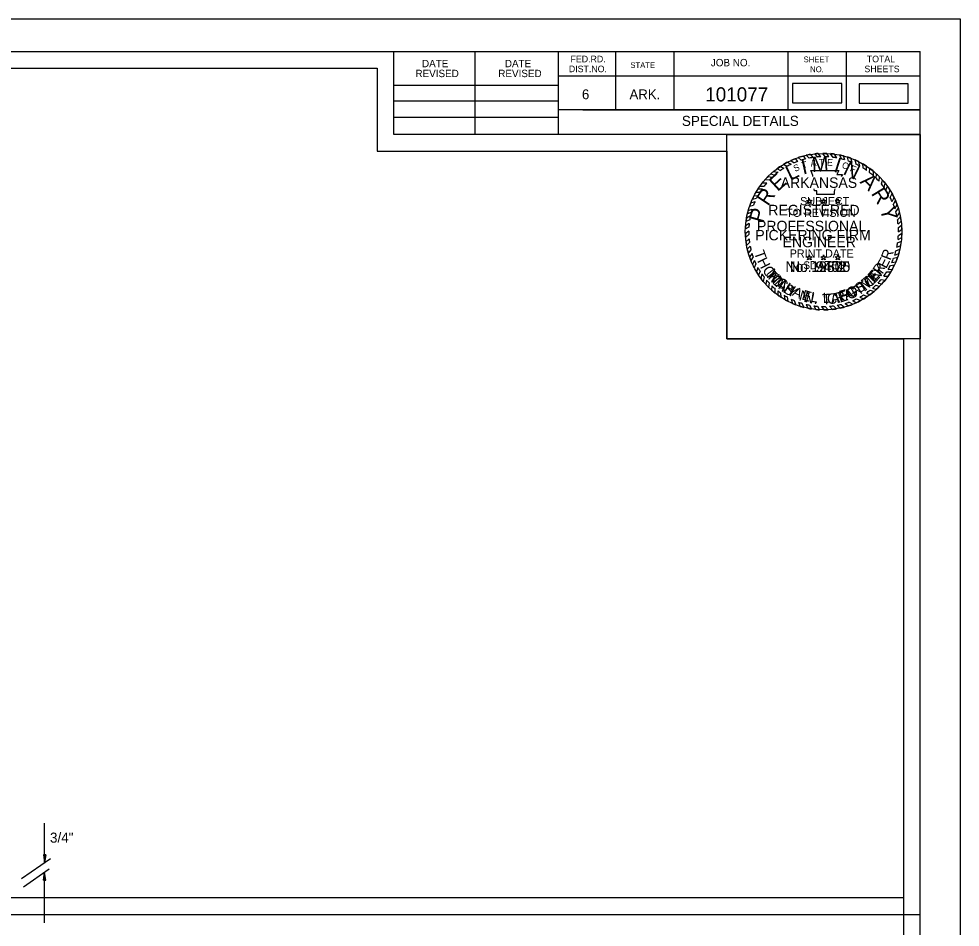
# Model space of a CAD drawing. Extents: x 1372039 to 1372773, y 376713 to 376926.
# Drawn here: x 1372260.6 to 1372372.6, y 376817.9 to 376926 of the extents above; entities that cross this region are included whole.
import ezdxf

# ---------------------------------------------------------------- set-up
doc = ezdxf.new("R2010")
doc.units = 0
for name, color, linetype in [('Default', 7, 'Continuous'), ('R_Border', 7, 'Continuous'), ('R_Border Notes', 7, 'Continuous'), ('R_Border Plan-Plan', 7, 'Continuous'), ('R_No Plot', 7, 'Continuous'), ('STAMP_PE_CRAFTON', 7, 'Continuous'), ('STAMP_PE_FOSTER', 7, 'Continuous'), ('STAMP_PE_SEAL-INFO', 7, 'Continuous'), ('STAMP_PE_TAEGTMEYER', 7, 'Continuous'), ('STAMP_PE_TXT', 7, 'Continuous'), ('STAMP_PRELIMINARY', 7, 'Continuous')]:
    doc.layers.add(name, color=color, linetype=linetype)

msp = doc.modelspace()

# ---------------------------------------------------------------- linework, layer by layer
at = {"layer": 'Default'}
for p, q in [((1372263.67, 376825.56), (1372263.67, 376830.27)), ((1372263.54, 376826.49), (1372263.67, 376825.56)), ((1372263.8, 376826.49), (1372263.54, 376826.49)), ((1372263.58, 376826.49), (1372263.67, 376825.87)), ((1372263.58, 376826.49), (1372263.67, 376825.74)), ((1372263.62, 376826.49), (1372263.67, 376826.19)), ((1372263.62, 376826.49), (1372263.67, 376826.05)), ((1372263.8, 376826.49), (1372263.67, 376825.56)), ((1372263.71, 376826.49), (1372263.67, 376826.19)), ((1372263.76, 376826.49), (1372263.67, 376825.87)), ((1372263.8, 376826.49), (1372263.67, 376825.74)), ((1372263.76, 376826.49), (1372263.67, 376826.05)), ((1372263.67, 376826.49), (1372263.67, 376826.36)), ((1372263.71, 376826.49), (1372263.67, 376826.36)), ((1372260.92, 376823.65), (1372264.38, 376826.05)), ((1372261.18, 376822.68), (1372264.2, 376824.81)), ((1372263.54, 376823.47), (1372263.67, 376824.41)), ((1372263.58, 376823.47), (1372263.67, 376824.28)), ((1372263.67, 376818.37), (1372263.67, 376824.41)), ((1372263.8, 376823.47), (1372263.67, 376824.41)), ((1372263.8, 376823.47), (1372263.67, 376824.28)), ((1372263.54, 376823.47), (1372263.8, 376823.47)), ((1372263.58, 376823.47), (1372263.67, 376824.1)), ((1372263.62, 376823.47), (1372263.67, 376823.96)), ((1372263.62, 376823.47), (1372263.67, 376823.78)), ((1372263.76, 376823.47), (1372263.67, 376824.1)), ((1372263.76, 376823.47), (1372263.67, 376823.96)), ((1372263.71, 376823.47), (1372263.67, 376823.78)), ((1372263.71, 376823.47), (1372263.67, 376823.65)), ((1372263.67, 376823.47), (1372263.67, 376823.65))]:
    msp.add_line(p, q, dxfattribs=at)
for points in [[(1372352.7, 376916.01), (1372358.54, 376916.01), (1372358.54, 376918.32), (1372352.7, 376918.32)], [(1372360.64, 376915.96), (1372366.47, 376915.96), (1372366.47, 376918.27), (1372360.64, 376918.27)]]:
    msp.add_lwpolyline(points, close=True, dxfattribs=at)
at = {"layer": 'R_Border'}
for p, q in [((1372051.71, 376922.11), (1372367.89, 376922.11)), ((1372305.25, 376912.23), (1372305.25, 376922.11)), ((1372314.93, 376912.23), (1372314.93, 376922.11)), ((1372324.79, 376922.11), (1372324.79, 376912.23)), ((1372331.63, 376922.11), (1372331.63, 376915.17)), ((1372338.57, 376922.11), (1372338.57, 376915.17)), ((1372352.15, 376922.11), (1372352.15, 376915.17)), ((1372359.09, 376922.11), (1372359.09, 376915.17)), ((1372367.89, 376716.65), (1372367.89, 376922.11)), ((1372367.89, 376919.17), (1372324.79, 376919.17)), ((1372367.89, 376919.19), (1372367.89, 376919.19)), ((1372305.25, 376918.09), (1372324.79, 376918.09)), ((1372305.25, 376916.23), (1372324.79, 376916.23)), ((1372367.89, 376915.17), (1372324.79, 376915.17)), ((1372327.75, 376915.17), (1372367.89, 376915.17)), ((1372305.25, 376914.29), (1372324.79, 376914.29)), ((1372367.89, 376912.23), (1372305.25, 376912.23))]:
    msp.add_line(p, q, dxfattribs=at)
at = {"layer": 'R_Border Plan-Plan'}
msp.add_line((1372051.71, 376819.38), (1372367.89, 376819.38), dxfattribs=at)
at = {"layer": 'R_No Plot'}
msp.add_line((1372039.31, 376926), (1372372.64, 376926), dxfattribs=at)
for points in [[(1372039.3, 376926), (1372372.64, 376926), (1372372.64, 376712.66), (1372039.3, 376712.66)], [(1372053.71, 376920.11), (1372303.25, 376920.11), (1372303.25, 376910.23), (1372320.79, 376910.23), (1372344.89, 376910.23), (1372344.89, 376887.89), (1372365.89, 376887.89), (1372365.89, 376718.65), (1372053.71, 376718.65)], [(1372365.89, 376821.38), (1372053.71, 376821.38), (1372053.71, 376920.11), (1372303.25, 376920.11), (1372303.25, 376910.23), (1372320.79, 376910.23), (1372344.89, 376910.23), (1372344.89, 376887.89), (1372365.89, 376887.89)], [(1372344.89, 376912.23), (1372367.89, 376912.23), (1372367.89, 376887.89), (1372344.89, 376887.89)]]:
    msp.add_lwpolyline(points, close=True, dxfattribs=at)
at = {"layer": 'STAMP_PE_SEAL-INFO'}
for p, q in [((1372353, 376909.36), (1372353.3, 376909.03)), ((1372353.35, 376909.48), (1372353.73, 376909.18)), ((1372353.94, 376909.67), (1372354.23, 376909.32)), ((1372354.33, 376909.76), (1372354.69, 376909.42)), ((1372354.81, 376909.86), (1372355.11, 376909.49)), ((1372355.33, 376909.93), (1372355.61, 376909.55)), ((1372356.06, 376909.58), (1372355.75, 376909.97)), ((1372356.56, 376909.58), (1372356.28, 376909.99)), ((1372357.02, 376909.56), (1372356.76, 376909.99)), ((1372357.52, 376909.51), (1372357.23, 376909.95)), ((1372357.95, 376909.45), (1372357.69, 376909.9)), ((1372358.51, 376909.33), (1372358.34, 376909.79)), ((1372358.91, 376909.22), (1372358.75, 376909.69)), ((1372359.37, 376909.07), (1372359.22, 376909.55)), ((1372359.78, 376908.91), (1372359.64, 376909.41)), ((1372351.23, 376908.43), (1372351.67, 376908.23)), ((1372351.62, 376908.68), (1372352.05, 376908.45)), ((1372352.06, 376908.93), (1372352.53, 376908.7)), ((1372352.5, 376909.14), (1372352.88, 376908.86)), ((1372360.25, 376908.71), (1372360.14, 376909.2)), ((1372360.69, 376908.48), (1372360.6, 376908.99)), ((1372361.08, 376908.25), (1372361.04, 376908.75)), ((1372361.51, 376907.96), (1372361.48, 376908.48)), ((1372349.75, 376907.22), (1372350.3, 376907.17)), ((1372350.09, 376907.54), (1372350.55, 376907.4)), ((1372350.43, 376907.84), (1372350.96, 376907.74)), ((1372350.81, 376908.17), (1372351.26, 376907.96)), ((1372354.86, 376907.96), (1372358.21, 376907.96)), ((1372354.99, 376907.65), (1372354.86, 376907.96)), ((1372355.09, 376907.36), (1372354.99, 376907.65)), ((1372355.1, 376907.24), (1372355.09, 376907.36)), ((1372358.21, 376907.96), (1372357.98, 376907.47)), ((1372357.98, 376907.47), (1372358.62, 376907.47)), ((1372358.62, 376907.47), (1372358.47, 376907.24)), ((1372361.87, 376907.7), (1372361.91, 376908.18)), ((1372362.32, 376907.33), (1372362.34, 376907.85)), ((1372362.63, 376907.03), (1372362.7, 376907.53)), ((1372362.99, 376906.66), (1372363.06, 376907.19)), ((1372348.81, 376906.09), (1372349.31, 376906.09)), ((1372349.08, 376906.46), (1372349.63, 376906.48)), ((1372349.43, 376906.87), (1372349.95, 376906.83)), ((1372363.27, 376906.34), (1372363.4, 376906.81)), ((1372363.59, 376905.93), (1372363.73, 376906.43)), ((1372363.81, 376905.61), (1372363.99, 376906.07)), ((1372348.09, 376904.92), (1372348.59, 376904.99)), ((1372348.33, 376905.35), (1372348.81, 376905.37)), ((1372348.57, 376905.75), (1372349.09, 376905.78)), ((1372355.29, 376905.53), (1372355.26, 376905.75)), ((1372355.6, 376905.53), (1372355.29, 376905.53)), ((1372355.6, 376905.1), (1372355.6, 376905.53)), ((1372357.63, 376905.1), (1372355.6, 376905.1)), ((1372357.65, 376905.44), (1372357.63, 376905.1)), ((1372357.73, 376905.75), (1372357.65, 376905.44)), ((1372364.12, 376905.11), (1372364.3, 376905.6)), ((1372364.32, 376904.75), (1372364.54, 376905.19)), ((1372347.57, 376903.69), (1372348.06, 376903.83)), ((1372347.72, 376904.1), (1372348.23, 376904.25)), ((1372347.91, 376904.53), (1372348.41, 376904.64)), ((1372364.55, 376904.26), (1372364.77, 376904.75)), ((1372364.69, 376903.93), (1372364.95, 376904.36)), ((1372364.88, 376903.38), (1372365.15, 376903.85)), ((1372347.31, 376902.78), (1372347.78, 376902.98)), ((1372347.42, 376903.19), (1372347.89, 376903.36)), ((1372364.99, 376903.01), (1372365.29, 376903.46)), ((1372365.12, 376902.45), (1372365.44, 376902.9)), ((1372347.53, 376901.64), (1372347.09, 376901.36)), ((1372347.59, 376902.08), (1372347.14, 376901.86)), ((1372347.68, 376902.54), (1372347.21, 376902.29)), ((1372365.19, 376902.07), (1372365.55, 376902.43)), ((1372365.26, 376901.56), (1372365.63, 376901.9)), ((1372347.49, 376901.22), (1372347.07, 376900.96)), ((1372347.48, 376900.73), (1372347.07, 376900.39)), ((1372365.29, 376901.15), (1372365.68, 376901.44)), ((1372365.29, 376900.22), (1372365.71, 376900.5)), ((1372365.3, 376900.63), (1372365.71, 376900.95)), ((1372347.48, 376900.32), (1372347.09, 376899.99)), ((1372347.52, 376899.82), (1372347.15, 376899.47)), ((1372347.57, 376899.39), (1372347.22, 376899.02)), ((1372365.2, 376899.33), (1372365.65, 376899.55)), ((1372365.25, 376899.72), (1372365.69, 376899.97)), ((1372347.65, 376898.93), (1372347.31, 376898.57)), ((1372347.74, 376898.52), (1372347.43, 376898.1)), ((1372365, 376898.38), (1372365.48, 376898.58)), ((1372365.11, 376898.83), (1372365.57, 376899.02)), ((1372347.87, 376898.07), (1372347.57, 376897.65)), ((1372348.01, 376897.65), (1372347.72, 376897.23)), ((1372348.17, 376897.22), (1372347.91, 376896.8)), ((1372364.51, 376896.99), (1372365, 376897.08)), ((1372364.72, 376897.5), (1372365.21, 376897.63)), ((1372364.86, 376897.88), (1372365.35, 376898.08)), ((1372348.34, 376896.84), (1372348.12, 376896.37)), ((1372348.58, 376896.38), (1372348.39, 376895.89)), ((1372348.82, 376895.97), (1372348.63, 376895.5)), ((1372363.9, 376895.87), (1372364.38, 376895.87)), ((1372364.08, 376896.15), (1372364.58, 376896.21)), ((1372364.35, 376896.65), (1372364.84, 376896.72)), ((1372349.02, 376895.66), (1372348.91, 376895.11)), ((1372349.3, 376895.27), (1372349.2, 376894.74)), ((1372349.6, 376894.89), (1372349.52, 376894.37)), ((1372363.26, 376894.98), (1372363.72, 376894.91)), ((1372363.56, 376895.38), (1372364.07, 376895.38)), ((1372349.9, 376894.56), (1372349.84, 376894.03)), ((1372350.23, 376894.23), (1372350.2, 376893.7)), ((1372350.57, 376893.92), (1372350.57, 376893.39)), ((1372361.94, 376893.7), (1372362.41, 376893.55)), ((1372362.21, 376893.92), (1372362.68, 376893.79)), ((1372362.62, 376894.29), (1372363.06, 376894.15)), ((1372362.87, 376894.55), (1372363.35, 376894.47)), ((1372350.93, 376893.62), (1372350.95, 376893.1)), ((1372351.27, 376893.37), (1372351.31, 376892.86)), ((1372351.7, 376893.09), (1372351.76, 376892.58)), ((1372352.05, 376892.89), (1372352.14, 376892.37)), ((1372352.53, 376892.64), (1372352.69, 376892.12)), ((1372360.32, 376892.67), (1372360.8, 376892.46)), ((1372360.72, 376892.88), (1372361.14, 376892.65)), ((1372361.14, 376893.13), (1372361.59, 376892.93)), ((1372361.48, 376893.35), (1372361.92, 376893.16)), ((1372352.9, 376892.47), (1372353.07, 376891.96)), ((1372353.39, 376892.28), (1372353.6, 376891.77)), ((1372353.8, 376892.14), (1372354.03, 376891.65)), ((1372354.31, 376892), (1372354.52, 376891.54)), ((1372354.71, 376891.92), (1372354.96, 376891.46)), ((1372355.21, 376891.84), (1372355.45, 376891.39)), ((1372355.65, 376891.79), (1372355.92, 376891.36)), ((1372356.13, 376891.76), (1372356.43, 376891.35)), ((1372356.59, 376891.76), (1372356.93, 376891.36)), ((1372357.11, 376891.79), (1372357.43, 376891.41)), ((1372357.55, 376891.83), (1372357.92, 376891.47)), ((1372357.99, 376891.9), (1372358.38, 376891.56)), ((1372358.48, 376892.01), (1372358.86, 376891.68)), ((1372358.94, 376892.13), (1372359.36, 376891.83)), ((1372359.44, 376892.29), (1372359.88, 376892.02)), ((1372359.86, 376892.46), (1372360.28, 376892.2))]:
    msp.add_line(p, q, dxfattribs=at)
for radius, start, end in [(9.32, 111.3124, 114.7026), (9.32, 105.2339, 109.0352), (8.91, 104.0352, 107.3615), (9.32, 99.7525, 102.7765), (8.91, 98.258, 101.0329), (9.32, 93.9381, 96.5517), (8.91, 92.1102, 95.0367), (9.32, 87.7298, 90.6707), (8.91, 85.9628, 88.9097), (9.32, 81.9732, 84.8236), (8.91, 79.9264, 82.696), (9.32, 75.3125, 77.9426), (8.91, 73.5575, 76.2314), (9.32, 69.6061, 72.3058), (9.32, 123.6199, 126.5906), (8.91, 121.9746, 125.11), (9.32, 117.6544, 120.8099), (8.91, 115.6869, 119.1583), (8.91, 110.3086, 113.1659), (8.91, 67.6248, 70.504), (9.32, 63.1329, 66.2704), (8.91, 61.1558, 64.3784), (9.32, 56.9003, 60.0942), (8.91, 54.9238, 58.2702), (9.32, 135.4021, 138.3031), (8.91, 133.1331, 136.2562), (9.32, 129.7326, 132.5376), (8.91, 127.5297, 130.9683), (8.91, 48.3016, 52.0395), (9.32, 50.3492, 53.7159), (9.32, 44.3405, 47.3929), (9.32, 141.6056, 144.4486), (8.91, 139.301, 142.5873), (8.91, 42.2212, 45.5512), (8.91, 36.135, 39.5311), (9.32, 38.1247, 41.2316), (9.32, 31.9614, 35.4294), (9.32, 152.864, 155.5189), (9.32, 147.0072, 149.899), (8.91, 151.0315, 153.573), (8.91, 145.0197, 148.2104), (8.91, 29.9032, 33.6645), (9.32, 25.9391, 29.0125), (9.32, 158.4077, 161.0701), (8.91, 156.3402, 159.2319), (8.91, 23.7732, 27.2211), (8.91, 17.6802, 21.4251), (9.32, 19.9538, 23.3141), (9.32, 164.3068, 166.894), (8.91, 162.4331, 165.0013), (8.91, 11.5444, 15.2364), (9.32, 13.8421, 17.4447), (9.32, 170.0003, 172.6878), (8.91, 173.73, 176.4734), (8.91, 167.9048, 170.9039), (8.91, 5.7599, 9.0606), (9.32, 7.5852, 10.8621), (9.32, 175.7409, 178.2066), (9.32, 181.7251, 184.1626), (8.91, 179.6454, 182.2633), (8.91, 359.7329, 3.0639), (9.32, 1.7215, 4.7268), (9.32, 355.7156, 358.9569), (9.32, 187.4204, 190.1927), (8.91, 185.4539, 188.234), (8.91, 348.0778, 351.3435), (8.91, 353.8632, 357.1274), (9.32, 349.8305, 353.0885), (9.32, 193.0369, 195.9973), (8.91, 191.2274, 193.9858), (8.91, 341.777, 345.0925), (9.32, 343.8925, 347.035), (9.32, 198.8967, 201.6281), (8.91, 196.9675, 199.8353), (8.91, 202.7761, 205.4791), (8.91, 335.6038, 339.1858), (9.32, 337.3837, 340.9933), (9.32, 204.5479, 207.4328), (9.32, 210.8636, 213.6571), (8.91, 208.7883, 211.7934), (8.91, 323.5851, 327.4407), (8.91, 329.5549, 333.2076), (9.32, 331.4037, 334.9332), (9.32, 216.6115, 219.491), (8.91, 214.1838, 217.2747), (8.91, 220.3909, 223.3056), (8.91, 316.6531, 320.3711), (9.32, 318.2846, 321.8043), (9.32, 325.4405, 328.9872), (9.32, 222.48, 225.3801), (9.32, 228.3665, 231.348), (8.91, 226.2494, 229.2407), (8.91, 304.823, 308.5143), (8.91, 310.7744, 314.3161), (9.32, 312.4518, 315.6633), (8.91, 232.229, 234.9336), (9.32, 234.295, 236.9452), (8.91, 238.2223, 240.8353), (9.32, 240.1977, 242.8613), (8.91, 244.3204, 246.9486), (8.91, 292.8745, 296.1185), (8.91, 299.0768, 302.1724), (9.32, 300.621, 303.8703), (9.32, 306.3721, 310.208), (9.32, 246.576, 249.1558), (8.91, 250.3491, 253.1216), (9.32, 252.5967, 255.3252), (8.91, 256.505, 259.1192), (9.32, 258.4433, 261.1398), (8.91, 262.3783, 265.2012), (9.32, 264.1978, 267.1009), (8.91, 268.3215, 271.277), (8.91, 274.6157, 277.4486), (9.32, 276.4239, 279.4357), (8.91, 280.3459, 283.5814), (9.32, 282.3199, 285.3702), (8.91, 286.6423, 289.9783), (9.32, 288.5709, 291.9733), (9.32, 294.6481, 298.2166), (9.32, 270.2548, 273.3361)]:
    msp.add_arc((1372356.39, 376900.67), radius, start, end, dxfattribs=at)
at = {"layer": 'STAMP_PE_TXT'}
for p, q in [((1372354.57, 376904.24), (1372354.37, 376904.39)), ((1372354.37, 376904.39), (1372354.62, 376904.39)), ((1372354.49, 376904.01), (1372354.57, 376904.24)), ((1372354.69, 376904.15), (1372354.49, 376904.01)), ((1372354.62, 376904.39), (1372354.69, 376904.62)), ((1372354.69, 376904.62), (1372354.77, 376904.39)), ((1372354.89, 376904.01), (1372354.69, 376904.15)), ((1372354.77, 376904.39), (1372355.01, 376904.39)), ((1372355.01, 376904.39), (1372354.82, 376904.24)), ((1372354.82, 376904.24), (1372354.89, 376904.01)), ((1372356.27, 376904.24), (1372356.07, 376904.39)), ((1372356.07, 376904.39), (1372356.32, 376904.39)), ((1372356.19, 376904.01), (1372356.27, 376904.24)), ((1372356.39, 376904.15), (1372356.19, 376904.01)), ((1372356.32, 376904.39), (1372356.39, 376904.62)), ((1372356.39, 376904.62), (1372356.47, 376904.39)), ((1372356.59, 376904.01), (1372356.39, 376904.15)), ((1372356.47, 376904.39), (1372356.71, 376904.39)), ((1372356.71, 376904.39), (1372356.51, 376904.24)), ((1372356.51, 376904.24), (1372356.59, 376904.01)), ((1372357.97, 376904.24), (1372357.77, 376904.39)), ((1372357.77, 376904.39), (1372358.01, 376904.39)), ((1372357.89, 376904.01), (1372357.97, 376904.24)), ((1372358.09, 376904.15), (1372357.89, 376904.01)), ((1372358.01, 376904.39), (1372358.09, 376904.62)), ((1372358.09, 376904.62), (1372358.16, 376904.39)), ((1372358.29, 376904.01), (1372358.09, 376904.15)), ((1372358.16, 376904.39), (1372358.41, 376904.39)), ((1372358.41, 376904.39), (1372358.21, 376904.24)), ((1372358.21, 376904.24), (1372358.29, 376904.01)), ((1372354.57, 376897.53), (1372354.37, 376897.68)), ((1372354.37, 376897.68), (1372354.62, 376897.68)), ((1372354.49, 376897.3), (1372354.57, 376897.53)), ((1372354.69, 376897.45), (1372354.49, 376897.3)), ((1372354.62, 376897.68), (1372354.69, 376897.91)), ((1372354.69, 376897.91), (1372354.77, 376897.68)), ((1372354.89, 376897.3), (1372354.69, 376897.45)), ((1372354.77, 376897.68), (1372355.01, 376897.68)), ((1372355.01, 376897.68), (1372354.82, 376897.53)), ((1372354.82, 376897.53), (1372354.89, 376897.3)), ((1372356.27, 376897.53), (1372356.07, 376897.68)), ((1372356.07, 376897.68), (1372356.32, 376897.68)), ((1372356.19, 376897.3), (1372356.27, 376897.53)), ((1372356.39, 376897.45), (1372356.19, 376897.3)), ((1372356.32, 376897.68), (1372356.39, 376897.91)), ((1372356.39, 376897.91), (1372356.47, 376897.68)), ((1372356.59, 376897.3), (1372356.39, 376897.45)), ((1372356.47, 376897.68), (1372356.71, 376897.68)), ((1372356.71, 376897.68), (1372356.51, 376897.53)), ((1372356.51, 376897.53), (1372356.59, 376897.3)), ((1372357.97, 376897.53), (1372357.77, 376897.68)), ((1372357.77, 376897.68), (1372358.01, 376897.68)), ((1372357.89, 376897.3), (1372357.97, 376897.53)), ((1372358.09, 376897.45), (1372357.89, 376897.3)), ((1372358.01, 376897.68), (1372358.09, 376897.91)), ((1372358.09, 376897.91), (1372358.16, 376897.68)), ((1372358.29, 376897.3), (1372358.09, 376897.45)), ((1372358.16, 376897.68), (1372358.41, 376897.68)), ((1372358.41, 376897.68), (1372358.21, 376897.53)), ((1372358.21, 376897.53), (1372358.29, 376897.3))]:
    msp.add_line(p, q, dxfattribs=at)
at = {"layer": 'STAMP_PRELIMINARY'}
msp.add_circle((1372356.39, 376900.67), 9.32, dxfattribs=at)

# ---------------------------------------------------------------- texts
at = {"layer": 'Default'}
msp.add_text('3/4"', height=1.2, dxfattribs=at).set_placement((1372264.31, 376827.93))
at = {"layer": 'R_Border'}
for s, height, p in [('DATE', 0.879, (1372308.59, 376920.24)), ('DATE', 0.879, (1372318.45, 376920.24)), ('FED.RD.', 0.782, (1372326.27, 376920.83)), ('STATE', 0.684, (1372333.39, 376920.15)), ('JOB NO.', 0.879, (1372342.97, 376920.35)), ('SHEET', 0.684, (1372354.01, 376920.83)), ('TOTAL', 0.782, (1372361.53, 376920.83)), ('REVISED', 0.879, (1372307.81, 376919.06)), ('REVISED', 0.879, (1372317.67, 376919.06)), ('DIST.NO.', 0.782, (1372326.07, 376919.65)), ('NO.', 0.684, (1372354.79, 376919.65)), ('SHEETS', 0.782, (1372361.25, 376919.65)), ('6', 1.17, (1372327.63, 376916.43)), ('ARK.', 1.172, (1372333.29, 376916.43))]:
    msp.add_text(s, height=height, dxfattribs=at).set_placement(p)
at = {"layer": 'R_Border Notes'}
for s, height, p in [('101077', 1.68, (1372342.3, 376916.17)), ('SPECIAL DETAILS', 1.2, (1372339.52, 376913.25))]:
    msp.add_text(s, height=height, dxfattribs=at).set_placement(p)
at = {"layer": 'STAMP_PE_CRAFTON'}
msp.add_text('No. 12370', height=1.25, dxfattribs=at).set_placement((1372351.85, 376895.87))
for s, rotation, p in [('T', 310.7442, (1372349.36, 376895.57)), ('N', 49.2411, (1372362.67, 376894.69)), ('O', 317.6422, (1372350.02, 376894.76)), ('N', 324.4537, (1372350.87, 376893.97)), ('T', 34.1136, (1372360.97, 376893.31)), ('O', 41.8391, (1372361.83, 376893.91)), ('Y', 331.1686, (1372351.9, 376893.26)), ('A', 20.5125, (1372359.07, 376892.43)), ('F', 28.7821, (1372360.05, 376892.8)), ('N', 347.4752, (1372353.96, 376892.34)), ('C', 6.0117, (1372356.86, 376892.01)), ('R', 14.8189, (1372357.96, 376892.13)), ('.', 356.8926, (1372355.19, 376892.06))]:
    msp.add_text(s, height=1.25, rotation=rotation, dxfattribs=at).set_placement(p)
at = {"layer": 'STAMP_PE_FOSTER'}
msp.add_text('No. 9402', height=1.25, dxfattribs=at).set_placement((1372352.38, 376895.87))
for s, rotation, p in [('M', 308.339, (1372349.51, 376895.69)), ('E', 46.9613, (1372362.39, 376894.66)), ('R', 54.5031, (1372363.12, 376895.48)), ('I', 314.1842, (1372350.3, 376894.75)), ('C', 319.8733, (1372350.66, 376894.4)), ('T', 39.4194, (1372361.53, 376893.91)), ('H', 327.7235, (1372351.59, 376893.66)), ('A', 335.7276, (1372352.57, 376893.08)), ('E', 343.5779, (1372353.71, 376892.61)), ('F', 15.8691, (1372358.43, 376892.42)), ('O', 23.719, (1372359.47, 376892.75)), ('S', 31.7234, (1372360.58, 376893.28)), ('L', 350.8115, (1372354.77, 376892.34)), ('L', 1.2666, (1372356.3, 376892.18)), ('.', 6.8035, (1372357.35, 376892.24))]:
    msp.add_text(s, height=1.2, rotation=rotation, dxfattribs=at).set_placement(p)
at = {"layer": 'STAMP_PE_TAEGTMEYER'}
for s, rotation, p in [('T', 289.646, (1372348.09, 376898.18)), ('R', 69.57, (1372364.34, 376897.18)), ('H', 296.7339, (1372348.45, 376897.2)), ('E', 63.0984, (1372363.84, 376896.2)), ('O', 303.7708, (1372349.04, 376896.09)), ('M', 314.2033, (1372349.69, 376895.14)), ('E', 46.8094, (1372362.43, 376894.45)), ('Y', 53.9986, (1372363.17, 376895.26)), ('A', 321.0594, (1372350.65, 376894.17)), ('M', 39.3, (1372361.39, 376893.57)), ('S', 327.8239, (1372351.48, 376893.53)), ('N', 344.2727, (1372353.38, 376892.52)), ('E', 17.6836, (1372358.34, 376892.2)), ('G', 23.3052, (1372359.39, 376892.53)), ('T', 31.466, (1372360.49, 376893.02)), ('T', 3.0061, (1372356.26, 376891.99)), ('A', 8.9826, (1372357.3, 376892.05)), ('.', 350.6464, (1372354.59, 376892.19))]:
    msp.add_text(s, height=1.25, rotation=rotation, dxfattribs=at).set_placement(p)
msp.add_text('No. 19605', height=1.25, dxfattribs=at).set_placement((1372351.85, 376895.87))
at = {"layer": 'STAMP_PE_TXT'}
for s, rotation, p in [('T', 1.8248, (1372355.86, 376908.53)), ('S', 23.5541, (1372352.99, 376907.77)), ('T', 16.311, (1372353.91, 376908.15)), ('A', 9.0679, (1372354.88, 376908.4)), ('E', 355.2002, (1372356.77, 376908.54)), ('O', 342.2506, (1372358.5, 376908.26)), ('F', 335.0075, (1372359.46, 376907.92))]:
    msp.add_text(s, height=0.781, rotation=rotation, dxfattribs=at).set_placement(p)
for s, p in [('ARKANSAS', (1372351.28, 376905.88)), ('REGISTERED', (1372349.81, 376902.61)), ('PROFESSIONAL', (1372348.46, 376900.71)), ('ENGINEER', (1372351.5, 376898.81))]:
    msp.add_text(s, height=1.25, dxfattribs=at).set_placement(p)
at = {"layer": 'STAMP_PRELIMINARY'}
for s, rotation, p in [('M', 3.1074, (1372355.03, 376907.77)), ('I', 342.3164, (1372357.49, 376907.83)), ('L', 25.513, (1372352.4, 376906.7)), ('I', 12.5248, (1372353.93, 376907.46)), ('N', 333.9382, (1372358.6, 376907.56)), ('E', 42.3578, (1372350.92, 376905.37)), ('A', 315.6579, (1372360.64, 376906.53)), ('R', 301.3831, (1372362, 376905.22)), ('R', 56.2292, (1372349.76, 376903.63)), ('Y', 283.2593, (1372363.09, 376903.43)), ('P', 73.913, (1372349.21, 376901.61))]:
    msp.add_text(s, height=1.8, rotation=rotation, dxfattribs=at).set_placement(p)
for s, height, p in [('SUBJECT', 0.96, (1372353.59, 376903.82)), ('TO REVISION', 0.96, (1372351.93, 376902.43)), ('PICKERING FIRM', 1.25, (1372348.26, 376899.63)), ('PRINT DATE', 0.96, (1372352.35, 376897.59)), ('$DATE$', 0.96, (1372354.03, 376896.2))]:
    msp.add_text(s, height=height, dxfattribs=at).set_placement(p)

doc.saveas('drawing.dxf')
